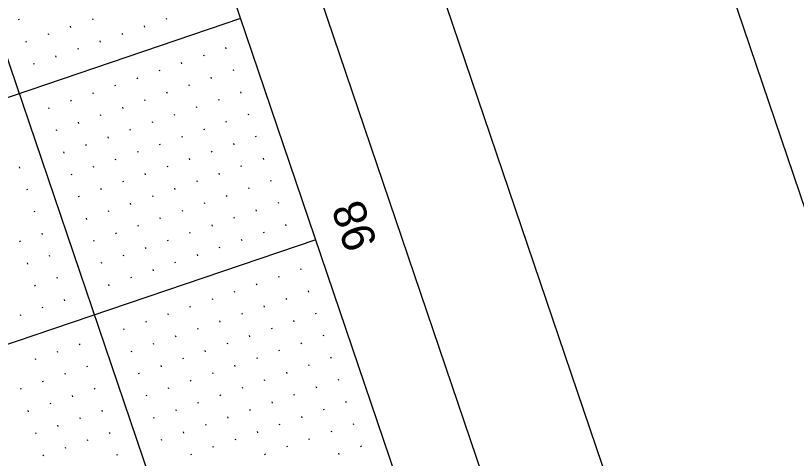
# Model space of a CAD drawing. Extents: x 2150318 to 2152065, y 143281 to 145371.
# Drawn here: x 2151482.1 to 2151649.1, y 144739.2 to 144834 of the extents above; entities that cross this region are included whole.
import ezdxf

# ---------------------------------------------------------------- set-up
doc = ezdxf.new("R2010")
doc.units = 0
for name, color, linetype in [('SHT_Plan_Profile_Sheet_Sta_Txt', 7, 'Continuous'), ('SHT_Plot_Shape_Full', 7, 'Continuous'), ('SHT_Plot_Shape_Half', 7, 'Continuous'), ('SHT_Profile_Grid_Major', 7, 'Continuous'), ('SHT_Profile_Grid_Minor', 7, 'Continuous'), ('SHT_Sheet_Border', 7, 'Continuous')]:
    doc.layers.add(name, color=color, linetype=linetype)

msp = doc.modelspace()

# ---------------------------------------------------------------- linework, layer by layer
at = {"layer": 'SHT_Plot_Shape_Full'}
msp.add_lwpolyline([(2150896.74, 143280.62), (2150318.46, 144985.2), (2151454.85, 145370.71), (2152033.12, 143666.13)], close=True, dxfattribs=at)
at = {"layer": 'SHT_Plot_Shape_Half'}
msp.add_lwpolyline([(2150909.49, 143371.4), (2150363.35, 144981.29), (2151405.04, 145334.68), (2151951.18, 143724.79)], close=True, dxfattribs=at)
at = {"layer": 'SHT_Profile_Grid_Major'}
for p, q in [((2151832.26, 143787.41), (2151326.27, 145278.92)), ((2151530.24, 144833.32), (2151056.74, 144672.69)), ((2151546.3, 144785.97), (2151072.81, 144625.34))]:
    msp.add_line(p, q, dxfattribs=at)
at = {"layer": 'SHT_Profile_Grid_Minor'}
for p, q in [((2151482.85, 144832.95), (2151482.77, 144833.19)), ((2151498.66, 144833.04), (2151498.58, 144833.27)), ((2151514.47, 144833.12), (2151514.39, 144833.36)), ((2151493.92, 144831.43), (2151493.84, 144831.67)), ((2151509.73, 144831.51), (2151509.65, 144831.75)), ((2151489.19, 144829.82), (2151489.11, 144830.06)), ((2151505, 144829.91), (2151504.92, 144830.14)), ((2151484.45, 144828.22), (2151484.37, 144828.45)), ((2151500.26, 144828.3), (2151500.18, 144828.54)), ((2151495.53, 144826.69), (2151495.45, 144826.93)), ((2151527.15, 144826.86), (2151527.07, 144827.1)), ((2151490.79, 144825.09), (2151490.71, 144825.32)), ((2151522.42, 144825.26), (2151522.34, 144825.49)), ((2151486.06, 144823.48), (2151485.98, 144823.72)), ((2151517.68, 144823.65), (2151517.6, 144823.89)), ((2151512.95, 144822.04), (2151512.87, 144822.28)), ((2151528.76, 144822.13), (2151528.68, 144822.36)), ((2151508.21, 144820.44), (2151508.13, 144820.67)), ((2151524.02, 144820.52), (2151523.94, 144820.76)), ((2151503.48, 144818.83), (2151503.4, 144819.07)), ((2151519.29, 144818.91), (2151519.21, 144819.15)), ((2151498.74, 144817.22), (2151498.66, 144817.46)), ((2151514.55, 144817.31), (2151514.47, 144817.55)), ((2151530.36, 144817.39), (2151530.28, 144817.63)), ((2151494.01, 144815.62), (2151493.93, 144815.85)), ((2151509.82, 144815.7), (2151509.74, 144815.94)), ((2151525.63, 144815.79), (2151525.55, 144816.02)), ((2151489.27, 144814.01), (2151489.19, 144814.25)), ((2151505.08, 144814.1), (2151505, 144814.33)), ((2151520.89, 144814.18), (2151520.81, 144814.42)), ((2151531.97, 144812.66), (2151531.89, 144812.89)), ((2151500.35, 144812.49), (2151500.27, 144812.73)), ((2151516.16, 144812.57), (2151516.08, 144812.81)), ((2151527.24, 144811.05), (2151527.16, 144811.29)), ((2151495.61, 144810.88), (2151495.53, 144811.12)), ((2151506.69, 144809.36), (2151506.61, 144809.6)), ((2151511.42, 144810.97), (2151511.34, 144811.2)), ((2151522.5, 144809.44), (2151522.42, 144809.68)), ((2151490.88, 144809.28), (2151490.8, 144809.51)), ((2151501.95, 144807.75), (2151501.87, 144807.99)), ((2151517.77, 144807.84), (2151517.69, 144808.08)), ((2151533.58, 144807.92), (2151533.5, 144808.16)), ((2151497.22, 144806.15), (2151497.14, 144806.38)), ((2151513.03, 144806.23), (2151512.95, 144806.47)), ((2151528.84, 144806.32), (2151528.76, 144806.55)), ((2151492.48, 144804.54), (2151492.4, 144804.78)), ((2151508.3, 144804.63), (2151508.22, 144804.86)), ((2151524.11, 144804.71), (2151524.03, 144804.95)), ((2151503.56, 144803.02), (2151503.48, 144803.26)), ((2151519.37, 144803.1), (2151519.29, 144803.34)), ((2151535.18, 144803.19), (2151535.1, 144803.42)), ((2151483.01, 144801.33), (2151482.93, 144801.57)), ((2151498.83, 144801.41), (2151498.75, 144801.65)), ((2151514.64, 144801.5), (2151514.56, 144801.73)), ((2151530.45, 144801.58), (2151530.37, 144801.82)), ((2151494.09, 144799.81), (2151494.01, 144800.04)), ((2151509.9, 144799.89), (2151509.82, 144800.13)), ((2151525.71, 144799.97), (2151525.63, 144800.21)), ((2151505.17, 144798.28), (2151505.09, 144798.52)), ((2151520.98, 144798.37), (2151520.9, 144798.61)), ((2151536.79, 144798.45), (2151536.71, 144798.69)), ((2151484.62, 144796.59), (2151484.54, 144796.83)), ((2151500.43, 144796.68), (2151500.35, 144796.92)), ((2151516.24, 144796.76), (2151516.16, 144797)), ((2151532.05, 144796.85), (2151531.97, 144797.08)), ((2151495.7, 144795.07), (2151495.62, 144795.31)), ((2151511.51, 144795.16), (2151511.43, 144795.39)), ((2151527.32, 144795.24), (2151527.24, 144795.48)), ((2151506.77, 144793.55), (2151506.69, 144793.79)), ((2151522.58, 144793.63), (2151522.5, 144793.87)), ((2151538.4, 144793.72), (2151538.32, 144793.95)), ((2151486.23, 144791.86), (2151486.15, 144792.1)), ((2151502.04, 144791.94), (2151501.96, 144792.18)), ((2151517.85, 144792.03), (2151517.77, 144792.26)), ((2151533.66, 144792.11), (2151533.58, 144792.35)), ((2151497.3, 144790.34), (2151497.22, 144790.57)), ((2151513.11, 144790.42), (2151513.03, 144790.66)), ((2151528.93, 144790.51), (2151528.85, 144790.74)), ((2151508.38, 144788.81), (2151508.3, 144789.05)), ((2151524.19, 144788.9), (2151524.11, 144789.14)), ((2151540, 144788.98), (2151539.92, 144789.22)), ((2151487.83, 144787.12), (2151487.75, 144787.36)), ((2151503.64, 144787.21), (2151503.56, 144787.45)), ((2151519.46, 144787.29), (2151519.38, 144787.53)), ((2151535.27, 144787.38), (2151535.19, 144787.61)), ((2151483.1, 144785.52), (2151483.02, 144785.75)), ((2151498.91, 144785.6), (2151498.83, 144785.84)), ((2151514.72, 144785.69), (2151514.64, 144785.92)), ((2151530.53, 144785.77), (2151530.45, 144786.01)), ((2151509.99, 144784.08), (2151509.91, 144784.32)), ((2151525.8, 144784.16), (2151525.72, 144784.4)), ((2151489.44, 144782.39), (2151489.36, 144782.63)), ((2151505.25, 144782.47), (2151505.17, 144782.71)), ((2151516.33, 144780.95), (2151516.25, 144781.19)), ((2151521.06, 144782.56), (2151520.98, 144782.79)), ((2151484.7, 144780.78), (2151484.62, 144781.02)), ((2151500.52, 144780.87), (2151500.44, 144781.1)), ((2151511.59, 144779.34), (2151511.51, 144779.58)), ((2151543.21, 144779.51), (2151543.13, 144779.75)), ((2151491.05, 144777.65), (2151490.97, 144777.89)), ((2151506.86, 144777.74), (2151506.78, 144777.98)), ((2151538.48, 144777.91), (2151538.4, 144778.14)), ((2151486.31, 144776.05), (2151486.23, 144776.28)), ((2151502.12, 144776.13), (2151502.04, 144776.37)), ((2151533.74, 144776.3), (2151533.66, 144776.54)), ((2151529.01, 144774.69), (2151528.93, 144774.93)), ((2151544.82, 144774.78), (2151544.74, 144775.01)), ((2151492.65, 144772.92), (2151492.57, 144773.16)), ((2151524.27, 144773.09), (2151524.19, 144773.32)), ((2151540.09, 144773.17), (2151540.01, 144773.41)), ((2151487.92, 144771.31), (2151487.84, 144771.55)), ((2151519.54, 144771.48), (2151519.46, 144771.72)), ((2151535.35, 144771.57), (2151535.27, 144771.8)), ((2151483.18, 144769.71), (2151483.1, 144769.94)), ((2151514.8, 144769.87), (2151514.72, 144770.11)), ((2151530.62, 144769.96), (2151530.54, 144770.2)), ((2151546.43, 144770.04), (2151546.35, 144770.28)), ((2151510.07, 144768.27), (2151509.99, 144768.51)), ((2151525.88, 144768.35), (2151525.8, 144768.59)), ((2151541.69, 144768.44), (2151541.61, 144768.67)), ((2151505.34, 144766.66), (2151505.25, 144766.9)), ((2151521.15, 144766.75), (2151521.07, 144766.98)), ((2151536.96, 144766.83), (2151536.88, 144767.07)), ((2151516.41, 144765.14), (2151516.33, 144765.38)), ((2151532.22, 144765.22), (2151532.14, 144765.46)), ((2151548.03, 144765.31), (2151547.95, 144765.54)), ((2151495.87, 144763.45), (2151495.78, 144763.69)), ((2151511.68, 144763.53), (2151511.6, 144763.77)), ((2151527.49, 144763.62), (2151527.41, 144763.85)), ((2151543.3, 144763.7), (2151543.22, 144763.94)), ((2151491.13, 144761.84), (2151491.05, 144762.08)), ((2151506.94, 144761.93), (2151506.86, 144762.16)), ((2151522.75, 144762.01), (2151522.67, 144762.25)), ((2151538.56, 144762.1), (2151538.48, 144762.33)), ((2151486.4, 144760.24), (2151486.31, 144760.47)), ((2151518.02, 144760.4), (2151517.94, 144760.64)), ((2151533.83, 144760.49), (2151533.75, 144760.73)), ((2151549.64, 144760.57), (2151549.56, 144760.81)), ((2151497.47, 144758.71), (2151497.39, 144758.95)), ((2151513.28, 144758.8), (2151513.2, 144759.04)), ((2151529.09, 144758.88), (2151529.01, 144759.12)), ((2151544.9, 144758.97), (2151544.82, 144759.2)), ((2151492.74, 144757.11), (2151492.66, 144757.35)), ((2151508.55, 144757.19), (2151508.47, 144757.43)), ((2151524.36, 144757.28), (2151524.28, 144757.51)), ((2151540.17, 144757.36), (2151540.09, 144757.6)), ((2151488, 144755.5), (2151487.92, 144755.74)), ((2151519.62, 144755.67), (2151519.54, 144755.91)), ((2151535.43, 144755.75), (2151535.35, 144755.99)), ((2151546.51, 144754.23), (2151546.43, 144754.47)), ((2151551.25, 144755.84), (2151551.17, 144756.07)), ((2151483.27, 144753.9), (2151483.19, 144754.13)), ((2151499.08, 144753.98), (2151499, 144754.22)), ((2151514.89, 144754.06), (2151514.81, 144754.3)), ((2151525.97, 144752.54), (2151525.88, 144752.78)), ((2151530.7, 144754.15), (2151530.62, 144754.38)), ((2151541.78, 144752.63), (2151541.7, 144752.86)), ((2151494.34, 144752.37), (2151494.26, 144752.61)), ((2151510.15, 144752.46), (2151510.07, 144752.69)), ((2151521.23, 144750.94), (2151521.15, 144751.17)), ((2151537.04, 144751.02), (2151536.96, 144751.26)), ((2151552.85, 144751.1), (2151552.77, 144751.34)), ((2151489.61, 144750.77), (2151489.53, 144751)), ((2151500.68, 144749.24), (2151500.6, 144749.48)), ((2151516.5, 144749.33), (2151516.41, 144749.57)), ((2151532.31, 144749.41), (2151532.23, 144749.65)), ((2151548.12, 144749.5), (2151548.04, 144749.73)), ((2151484.87, 144749.16), (2151484.79, 144749.4)), ((2151495.95, 144747.64), (2151495.87, 144747.88)), ((2151511.76, 144747.72), (2151511.68, 144747.96)), ((2151527.57, 144747.81), (2151527.49, 144748.04)), ((2151543.38, 144747.89), (2151543.3, 144748.13)), ((2151491.21, 144746.03), (2151491.13, 144746.27)), ((2151522.84, 144746.2), (2151522.76, 144746.44)), ((2151538.65, 144746.28), (2151538.57, 144746.52)), ((2151554.46, 144746.37), (2151554.38, 144746.6)), ((2151486.48, 144744.43), (2151486.4, 144744.66)), ((2151502.29, 144744.51), (2151502.21, 144744.75)), ((2151518.1, 144744.59), (2151518.02, 144744.83)), ((2151533.91, 144744.68), (2151533.83, 144744.91)), ((2151549.72, 144744.76), (2151549.64, 144745)), ((2151497.56, 144742.9), (2151497.48, 144743.14)), ((2151513.37, 144742.99), (2151513.29, 144743.22)), ((2151529.18, 144743.07), (2151529.1, 144743.31)), ((2151544.99, 144743.16), (2151544.91, 144743.39)), ((2151492.82, 144741.3), (2151492.74, 144741.53)), ((2151524.44, 144741.47), (2151524.36, 144741.7)), ((2151540.25, 144741.55), (2151540.17, 144741.79)), ((2151556.07, 144741.63), (2151555.98, 144741.87)), ((2151488.09, 144739.69), (2151488.01, 144739.93)), ((2151503.9, 144739.77), (2151503.82, 144740.01)), ((2151519.71, 144739.86), (2151519.63, 144740.1)), ((2151535.52, 144739.94), (2151535.44, 144740.18)), ((2151551.33, 144740.03), (2151551.25, 144740.26))]:
    msp.add_line(p, q, dxfattribs=at)
at = {"layer": 'SHT_Sheet_Border'}
msp.add_line((2151879.61, 143803.47), (2151457.96, 145046.39), dxfattribs=at)
msp.add_lwpolyline([(2150901.85, 143471.77), (2150395.86, 144963.28), (2151390.2, 145300.6), (2151896.19, 143809.09)], close=True, dxfattribs=at)

# ---------------------------------------------------------------- texts
at = {"layer": 'SHT_Plan_Profile_Sheet_Sta_Txt'}
msp.add_text('98', height=7, rotation=108.7393, dxfattribs=at).set_placement((2151559.53, 144785.13))

doc.saveas('drawing.dxf')
